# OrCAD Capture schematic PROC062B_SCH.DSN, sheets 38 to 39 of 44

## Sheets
38 38. TEST  HEADER: size C; title: TEST HEADER
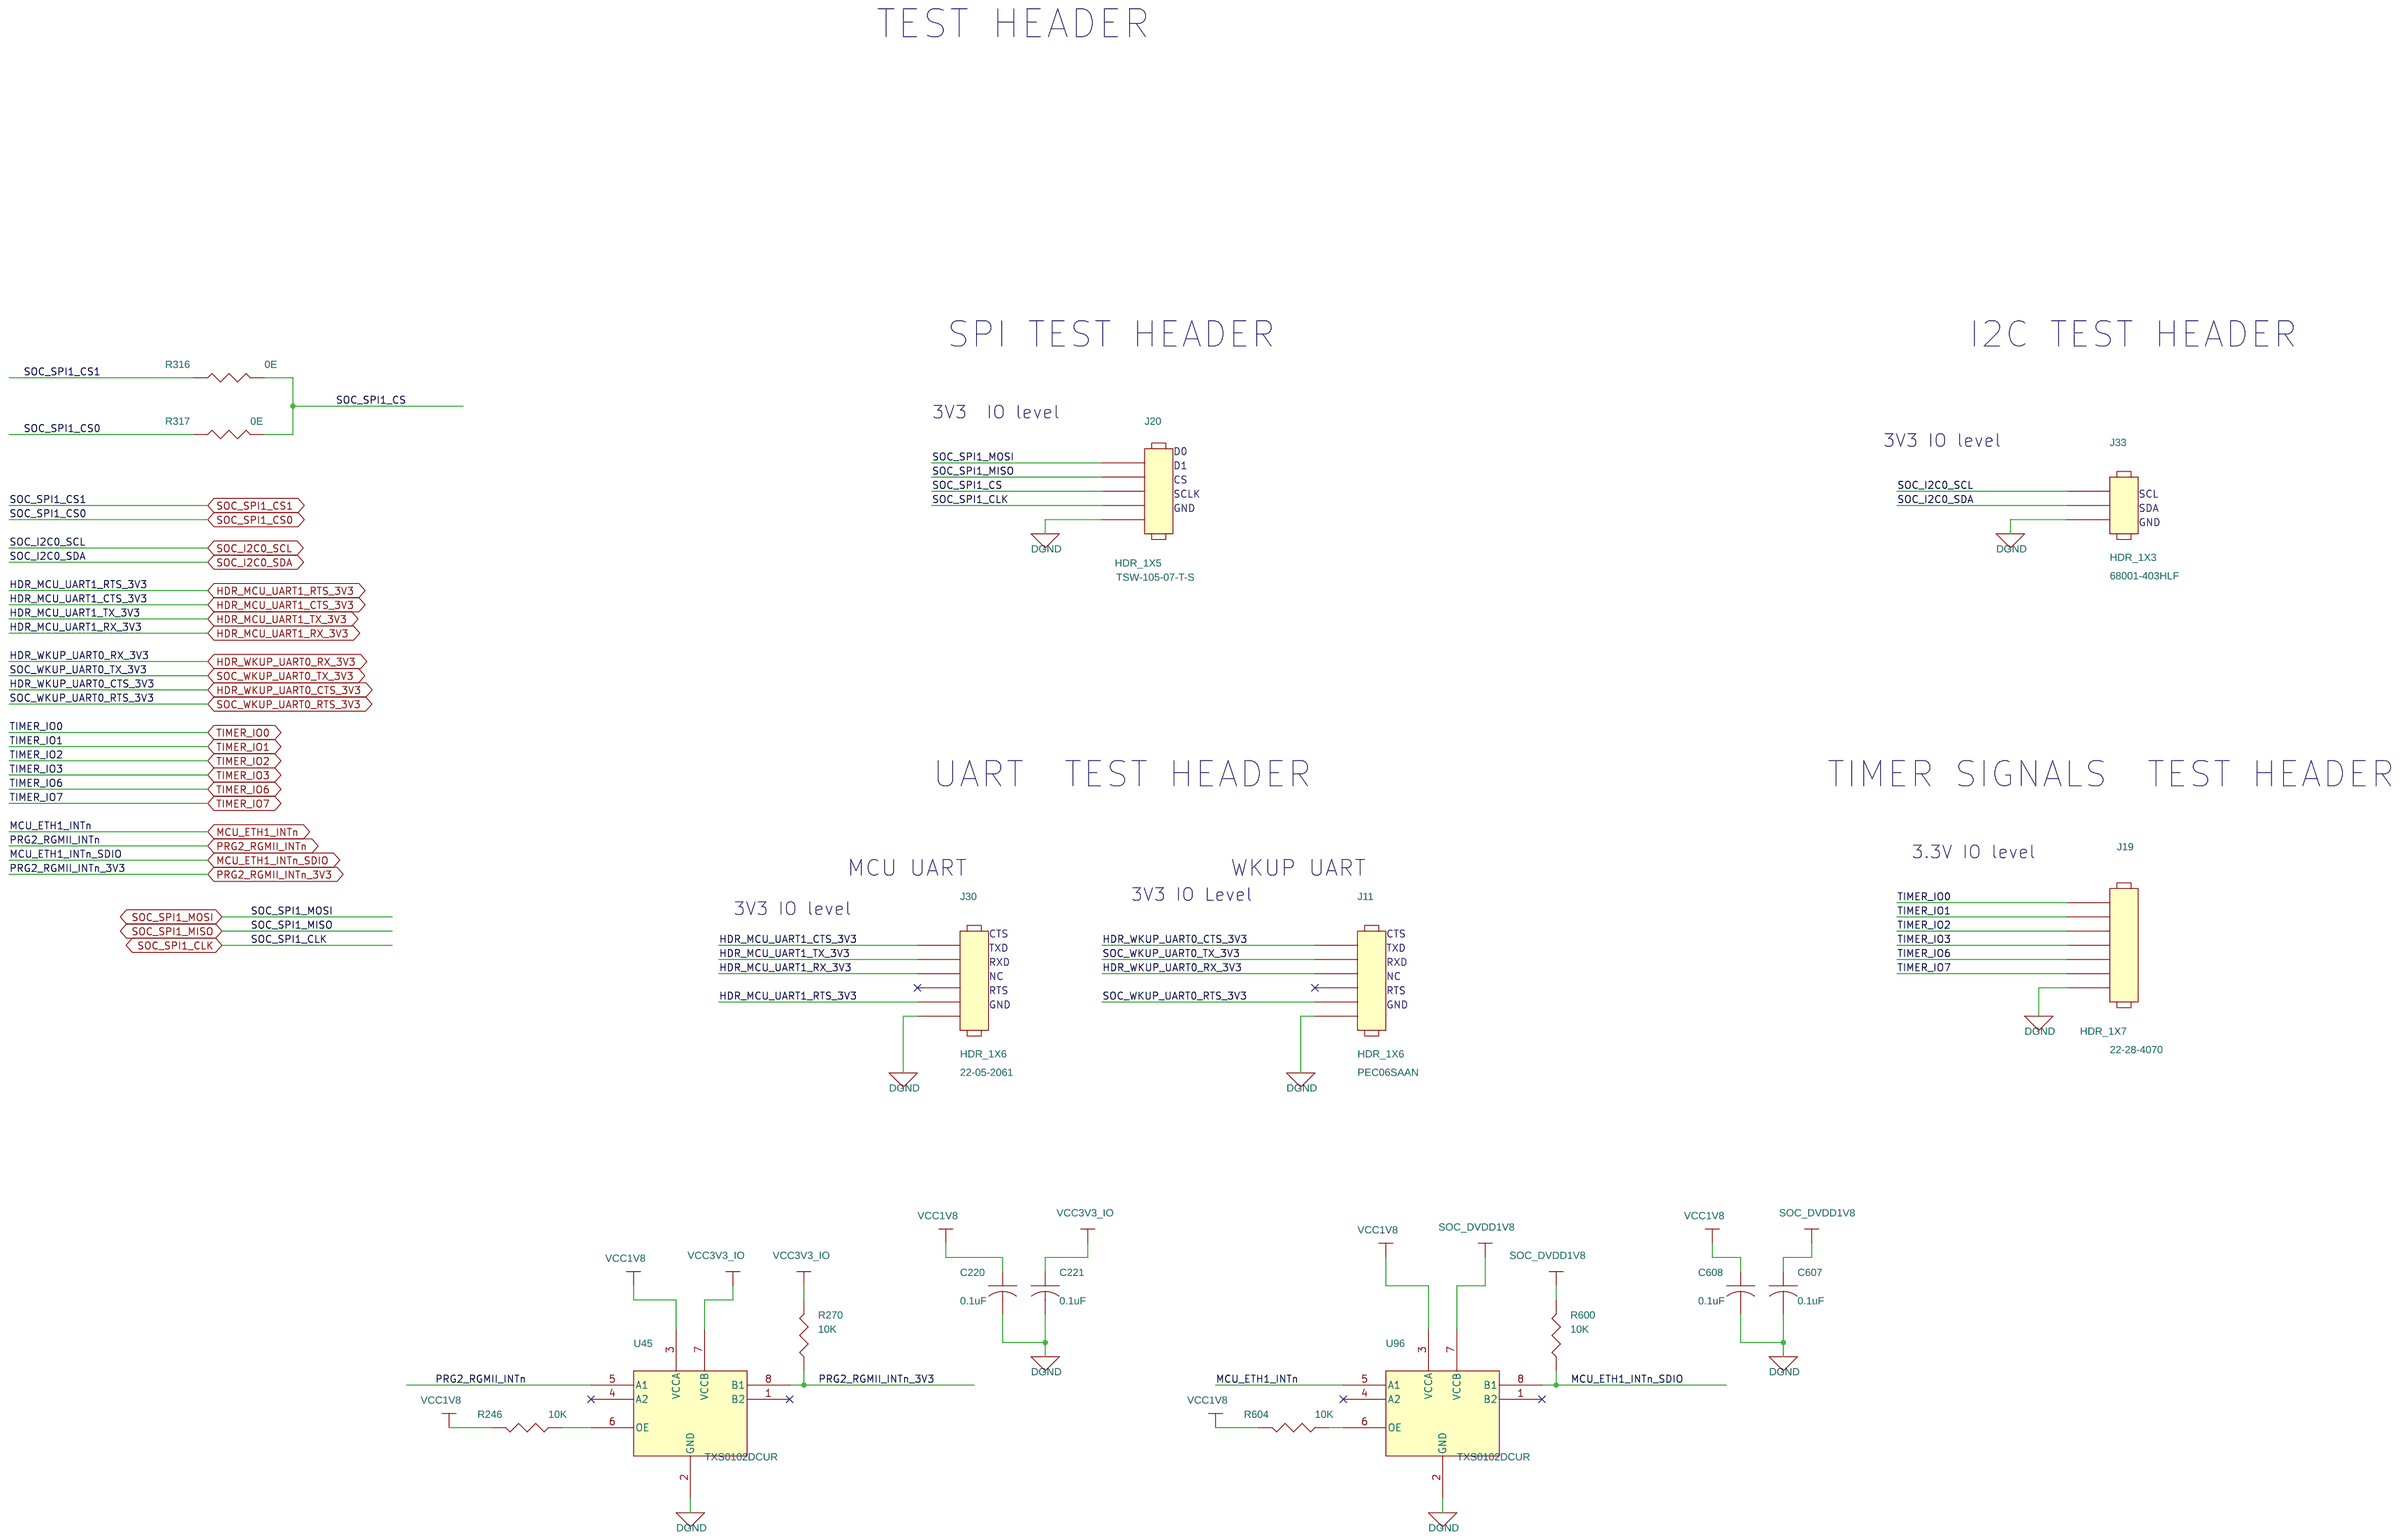
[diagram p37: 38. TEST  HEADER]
39 39. VOLTAGE SUPERVISOR: size C; title: VOLTAGE SUPERVISOR & WKUP LEDs
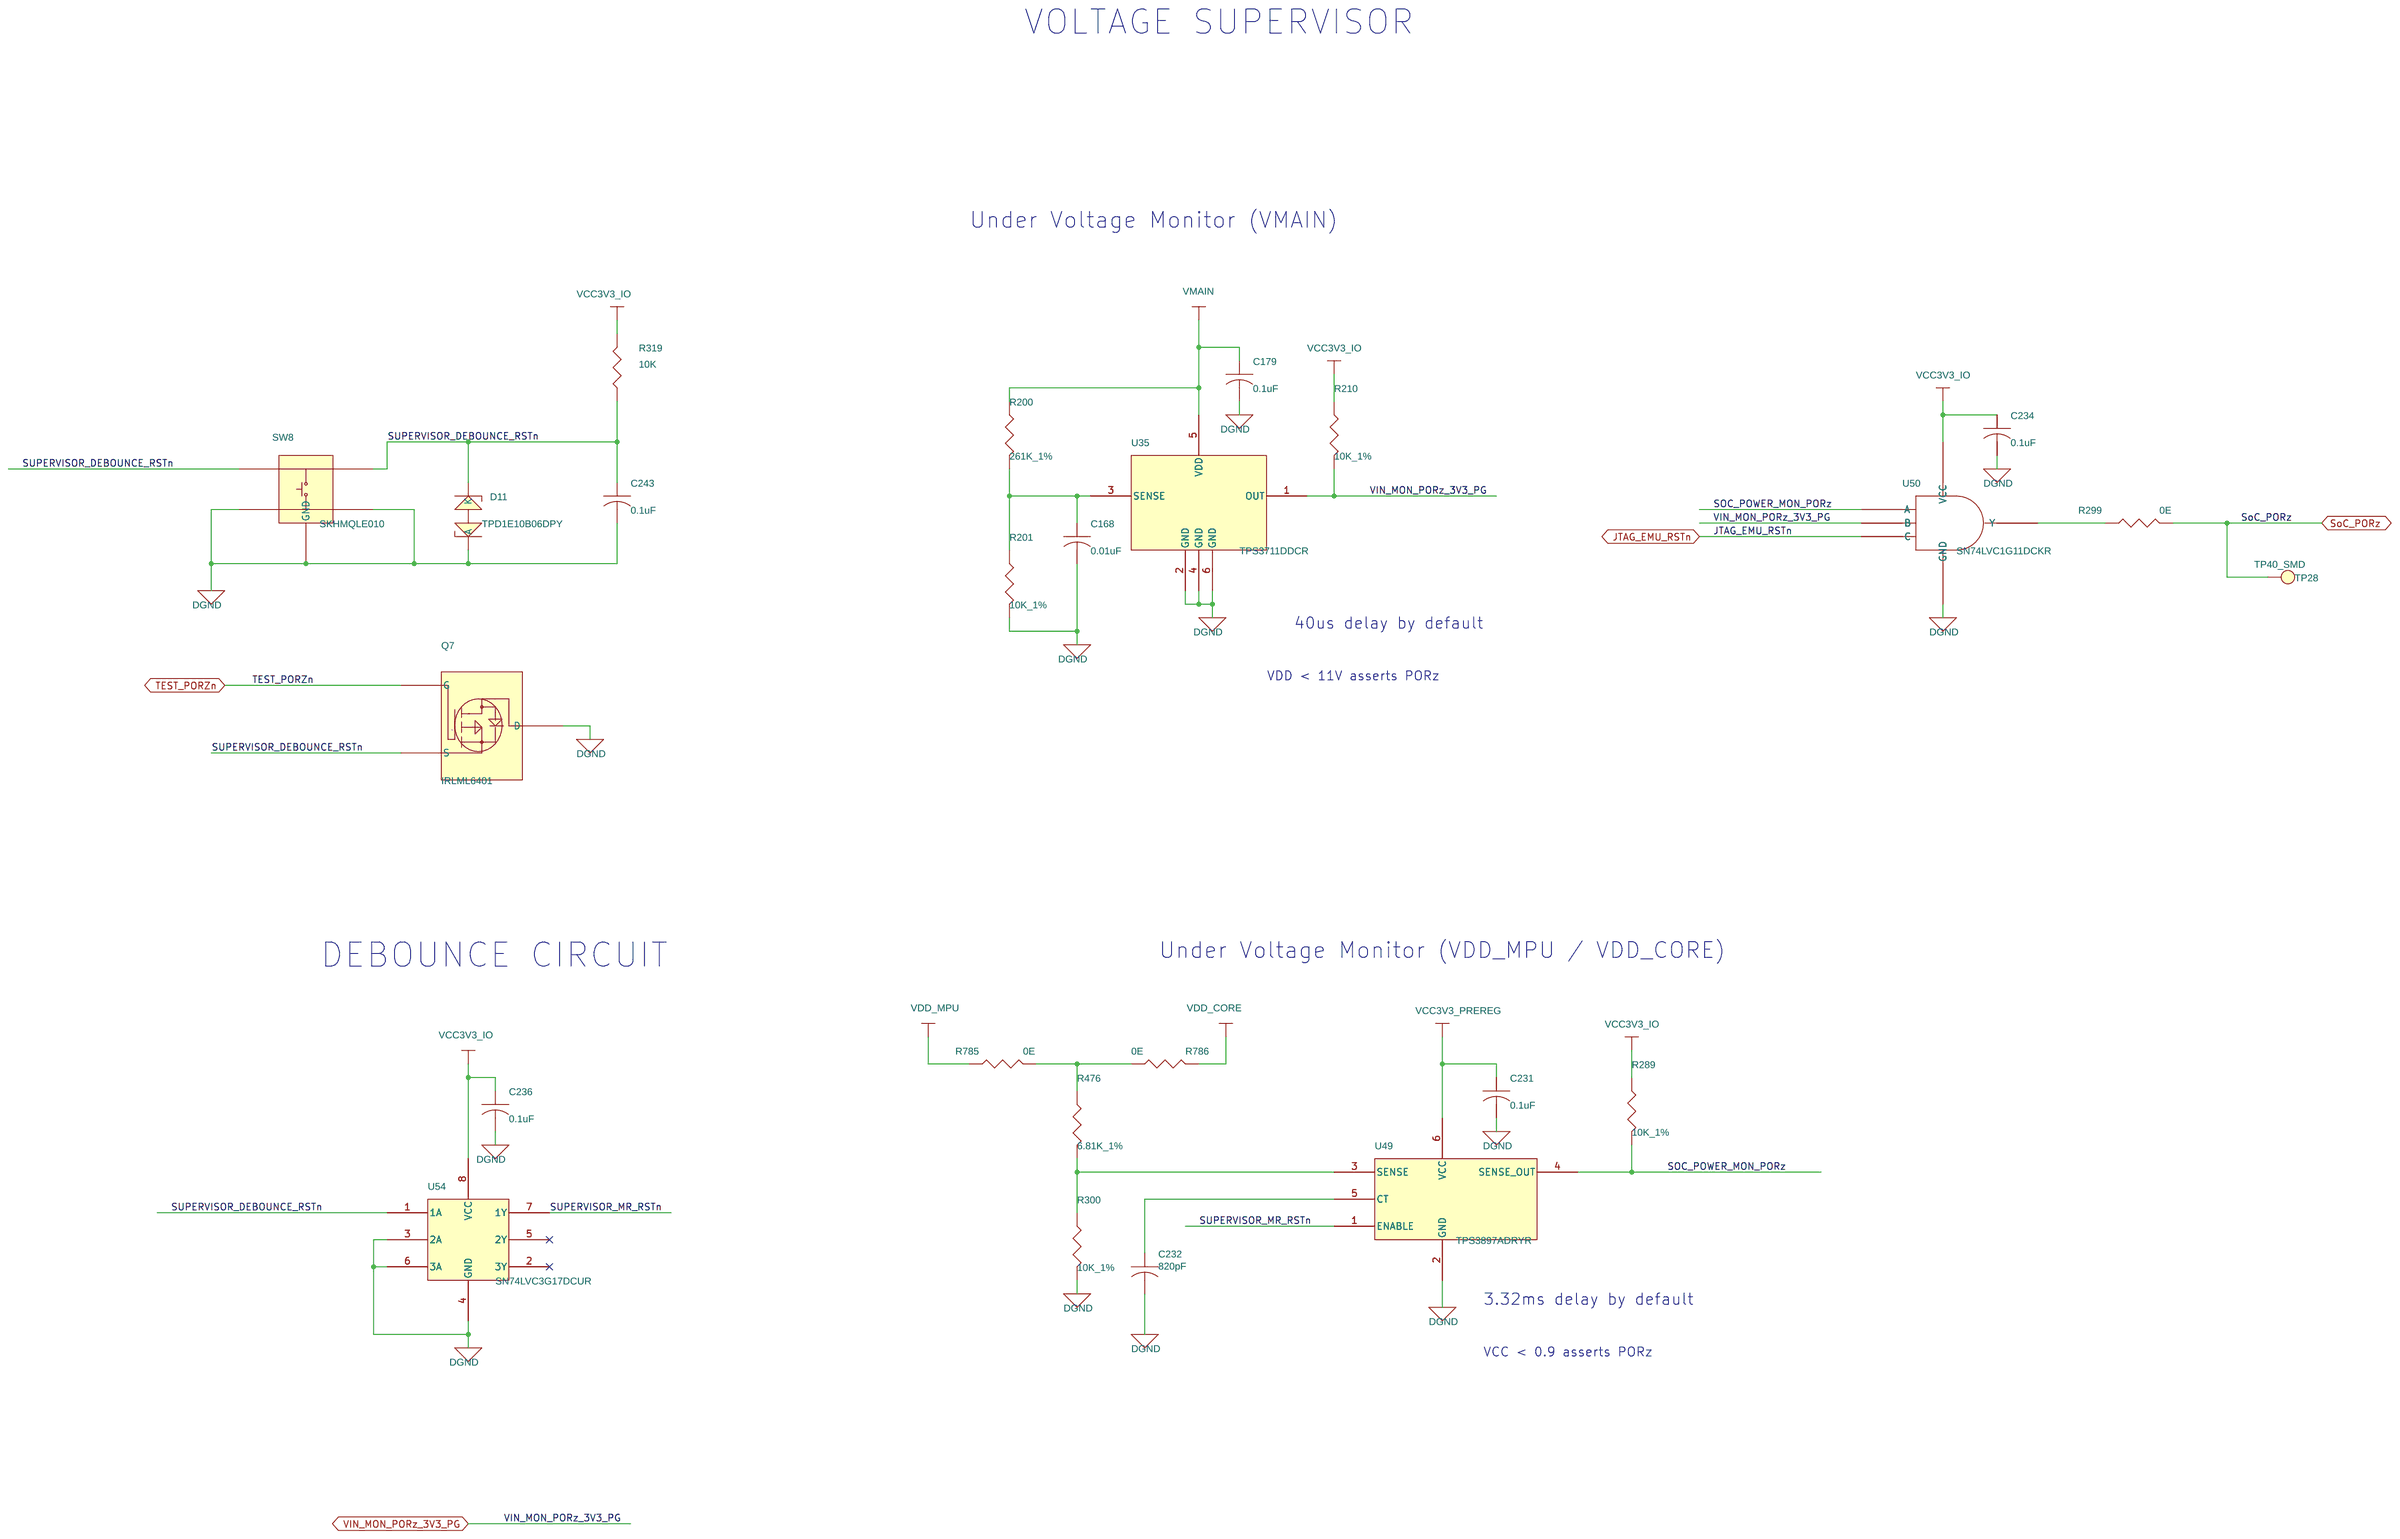
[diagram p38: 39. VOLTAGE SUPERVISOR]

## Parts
sheet 38. TEST  HEADER
C220  0.1uF  [CAP0201_0-5]
C221  0.1uF  [CAP0201_0-5]
C607  0.1uF  [CAP0201_0-5]
C608  0.1uF  [CAP0201_0-5]
J11  HDR_1X6  [HDR_6X1_100_S_T]
J19  HDR_1X7  [HDR_1X7_22284070_S_T_8-4]
J20  HDR_1X5  [HDR_5X1_100_S_T_8-4]
J30  HDR_1X6  [HDR_1X6_22052061_R_T_6-3]
J33  HDR_1X3  [HDR_3X1_100_S_T]
R246  10K  [RES0402_0-5]
R270  10K  [RES0402_0-5]
R316  0E  [RES0402_0-5]
R317  0E  [RES0402_0-5]
R600  10K  [RES0402_0-5]
R604  10K  [RES0402_0-5]
U45  TXS0102DCUR  [VSSOP8_19-68_85X95_0-9]
U96  TXS0102DCUR  [VSSOP8_19-68_85X95_0-9]
sheet 39. VOLTAGE SUPERVISOR
C168  0.01uF  [CAP0201_0-5]
C179  0.1uF  [CAP0603_1]
C231  0.1uF  [CAP0201_0-5]
C232  820pF  [CAP0402_0-75]
C234  0.1uF  [CAP0201_0-5]
C236  0.1uF  [CAP0201_0-5]
C243  0.1uF  [CAP0201_0-5]
D11  TPD1E10B06DPY  [DIO_DFN0402]
Q7  IRLML6401  [TO_SOT23-123]
R200  261K_1%  [RES0402_0-5]
R201  10K_1%  [RES0402_0-5]
R210  10K_1%  [RES0402_0-5]
R289  10K_1%  [RES0402_0-5]
R299  0E  [RES0402_0-5]
R300  10K_1%  [RES0402_0-5]
R319  10K  [RES0402_0-5]
R476  6.81K_1%  [RES0402_0-5]
R785  0E  [RES0402_0-5]
R786  0E  [RES0402_0-5]
SW8  SKHMQLE010  [SW4_SKHMQLE010_240X260_SMD_3-1]
TP28  TP40_SMD  [TP40_SMD]
U35  TPS3711DDCR  [SOT23-6_1-1]
U49  TPS3897ADRYR  [SON6_19-68_40X60_0-6]
U50  SN74LVC1G11DCKR  [SC70-6]
U54  SN74LVC3G17DCUR  [VSSOP8_19-68_85X95_0-9]

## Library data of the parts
C220 C221 C231 C234 C236 C243 C607 C608 = CAP: CAP CERAMIC 0.1uF 16V 10% X5R 0201; Chkd/date: MANIRAJA/120218; Crtd /date: MANIRAJA/120218; Custom_Duty: 15%; Customs_HS_Code: 85322990; Distributor_name: DIGIKEY; Distributor_part_number: 490-16742-1-ND; Height: 0.33MM; Mfr_name: MURATA; Mfr_part_number: GRM033R61C104KE84J; Mistral Part No: 120009030072-R; Package: 0201; Part_type: CAPACITORS\CERAMIC; Project: TI_MAXIE_CPB; RoHS: RoHS; Temperature: -55°C+85°C; Tolerance: 10%; Voltage: 16V; Wattage: NA; Weight: 0.33mg; Datasheet: Y:\MIS_DATABASE\DATASHEETS\CAPACITORS\GRM033R61C104KE84.PDF
J11 = HEADER_6X1: HDR 1X6 2.54 PITCH ST TH; Chkd/date: VASANTHA/220616; Crtd /date: VASANTHA/220616; Custom_Duty: 24%; Customs_HS_Code: 85369090; Distributor_name: DIGIKEY; Distributor_part_number: S1012E-06-ND; Height: 8.38MM; Mfr_name: SULLINS; Mfr_part_number: PEC06SAAN; Mistral Part No: 150016060022-R; Package: THRU HOLE; Part_type: CONNECTOR\HEADERS; Project: NTR_GPSDO BOX CARD; RoHS: RoHS; Temperature: -65°C+125°C; Tolerance: NA; Voltage: NA; Wattage: NA; Weight: NA; Datasheet: Y:\MIS_DATABASE\DATASHEETS\CONNECTORS\PECXXX_SERIES.PDF
J19 = HEADER_7X1: CON HDR 1X7 2.54MM PITCH ST TH; Chkd/date: MANIRAJA/230118; Crtd /date: ALVY/230118; Custom_Duty: 24%; Customs_HS_Code: 85369090; Distributor_name: DIGIKEY; Distributor_part_number: WM50014-07-ND; Height: 8.38MM; Mfr_name: MOLEX; Mfr_part_number: 22-28-4070; Mistral Part No: 150018010021-R; Package: THRU-HOLE; Part_type: CONNECTOR\HEADERS; Project: TI_MAXIE_CPB; RoHS: RoHS; Temperature: NA; Tolerance: NA; Voltage: NA; Wattage: NA; Weight: 431mg; Datasheet: Y:\MIS_DATABASE\DATASHEETS\CONNECTORS\22-28-SER.PDF
J20 = HEADER_5X1: CON HDR 1X5 2.54MM PITCH ST TH; Chkd/date: MANIRAJA/010917; Crtd /date: MANIRAJA/010917; Custom_Duty: 24%; Customs_HS_Code: 85369090; Distributor_name: DIGIKEY; Distributor_part_number: SAM1035-05-ND; Height: 8.38MM; Mfr_name: SAMTEC; Mfr_part_number: TSW-105-07-T-S; Mistral Part No: 150017090001-R; Package: THRU-HOLE; Part_type: CONNECTOR\HEADERS; Project: TI_MAXIE_CPB; RoHS: RoHS; Temperature: -55°C+105°C; Tolerance: NA; Voltage: NA; Wattage: NA; Weight: NA; Datasheet: Y:\MIS_DATABASE\DATASHEETS\CONNECTORS\TSW-MK.PDF
J30 = HEADER_6X1: CON HDR 1X6 2.54MM PITCH RT TH; Chkd/date: MANIRAJA/240118; Crtd /date: MANIRAJA/240118; Custom_Duty: 24%; Customs_HS_Code: 85369090; Distributor_name: DIGIKEY; Distributor_part_number: WM4104-ND; Height: 6.30MM; Mfr_name: MOLEX; Mfr_part_number: 22-05-2061; Mistral Part No: 150018010023-R; Package: THRU-HOLE; Part_type: CONNECTOR\HEADERS; Project: TI_MAXIE_CPB; RoHS: RoHS; Temperature: NA; Tolerance: NA; Voltage: NA; Wattage: NA; Weight: 484mg; Datasheet: Y:\MIS_DATABASE\DATASHEETS\CONNECTORS\A-4094-SER.PDF
J33 = HEADER_3X1: HDR 1X3 2.54MM PITCH ST TH; Chkd/date: VASANTHA/290616; Crtd /date: VASANTHA/290616; Custom_Duty: 15%; Customs_HS_Code: 85322990; Distributor_name: DIGIKEY; Distributor_part_number: 609-3471-ND; Height: 8.58MM; Mfr_name: FCI; Mfr_part_number: 68001-403HLF; Mistral Part No: 150016060025-R; Package: THRU-HOLE; Part_type: CONNECTOR\HEADERS; Project: IKEYP; RoHS: RoHS; Temperature: -40°C+105°C; Tolerance: NA; Voltage: NA; Wattage: NA; Weight: NA; Datasheet: Y:\MIS_DATABASE\DATASHEETS\CONNECTORS\68000.PDF
R246 R270 R319 R600 R604 = RESISTOR: RES 10K 1/16W 5% 0402; Chkd/date: VASANTHA/061216; Crtd /date: MAZHAR/230805; Custom_Duty: 15%; Customs_HS_Code: 85332119; Distributor_name: DIGIKEY; Distributor_part_number: 311-10KJRCT-ND; Footprint Path: Y:\MIS_DATABASE\Library\ALTIUM_TOOL\PCB_FOOTPRINTS\Altium_Footprint_Lib.PcbLib; Height: 0.40MM; Library Path: Y:\MIS_DATABASE\Library\ALTIUM_TOOL\SCHEMATICS_PARTS\MS_DISCRETE_Library.schlib; Mfr_name: YAGEO AMERICA; Mfr_part_number: RC0402JR-0710KL; Mistral Part No: 110009030208-R; Package: 0402; Part_type: RESISTORS\FIXED; Project: HSE; RoHS: Pb-Free; Temperature: -55°C+155°C; Tolerance: 5%; Voltage: NA; Wattage: 1/16W; Weight: 0.65mg; Datasheet: Y:\MIS_DATABASE\DATASHEETS\RESISTORS\YAGEO-RC0402.PDF
R299 R316 R317 R785 R786 = RESISTOR: RES 0E 1/16W 0402; Chkd/date: VASANTHA/201216; Crtd /date: MUDDU/190810; Custom_Duty: 15%; Customs_HS_Code: 85332119; Distributor_name: DIGIKEY; Distributor_part_number: 541-0.0JCT-ND; Footprint Path: Y:\MIS_DATABASE\Library\ALTIUM_TOOL\PCB_FOOTPRINTS\Altium_Footprint_Lib.PcbLib; Height: 0.40MM; Library Path: Y:\MIS_DATABASE\Library\ALTIUM_TOOL\SCHEMATICS_PARTS\MS_DISCRETE_Library.schlib; Mfr_name: VISHAY; Mfr_part_number: CRCW04020000Z0ED; Mistral Part No: 110010080019-P; Package: 0402; Part_type: RESISTORS\FIXED; Project: PB_BUGBASE; RoHS: Pb-Free; Temperature: -55°C+155°C; Tolerance: NA; Voltage: NA; Wattage: 1/16W; Weight: 0.65g/1000pcs; Datasheet: Y:\MIS_DATABASE\DATASHEETS\RESISTORS\CRCW0603.PDF
U45 U96 = TXS0102DCUR_VSSOP8: IC 2BIT BI-DIR VOLTAGE-LEVEL TRANSLATOR US8(VSSOP8); Chkd/date: MANIRAJA/130617; Crtd /date: SHREESHAIL/190108; Custom_Duty: 15%; Customs_HS_Code: 85423100; Distributor_name: DIGIKEY; Distributor_part_number: 296-21931-1-ND; Footprint Path: Y:\MIS_DATABASE\Library\ALTIUM_TOOL\PCB_FOOTPRINTS\Altium_Footprint_Lib.PcbLib; Height: 0.90MM; Library Path: Y:\MIS_DATABASE\Library\ALTIUM_TOOL\SCHEMATICS_PARTS\MS_MISCINTERFACE_Library.schlib; Mfr_name: TEXAS INSTRUMENTS; Mistral Part No: 141009030376-R; Package: US8; Part_type: ICS\INTERFACE\LEVEL TRANSLATOR; Project: SD_WATERLOO; RoHS: RoHS; Temperature: -40°C+85°C; Tolerance: NA; Voltage: NA; Wattage: NA; Weight: 9.6mg; Datasheet: Y:\MIS_DATABASE\DATASHEETS\ICS\INTERFACE\TXS0102.PDF
C168 = CAP: CAP CERAMIC 0.01uF 25V 10% X5R 0201; Chkd/date: MANIRAJA/230118; Crtd /date: MANIRAJA/230118; Custom_Duty: 15%; Customs_HS_Code: 85322990; Distributor_name: DIGIKEY; Distributor_part_number: GRM033R61E103KA12J-ND; Height: 0.33MM; Mfr_name: MURATA; Mfr_part_number: GRM033R61E103KA12J; Mistral Part No: 120018010007-R; Package: 0201; Part_type: CAPACITORS\CERAMIC; Project: TI_MAXIE_CPB; RoHS: RoHS; Temperature: -55°C+85°C; Tolerance: 10%; Voltage: 25V; Wattage: NA; Weight: 0.33mg; Datasheet: Y:\MIS_DATABASE\DATASHEETS\CAPACITORS\GRM033R61E103KA12.PDF
C179 = CAP: CAP CERAMIC 0.1uF 50V 20% X7R 0603; Chkd/date: MANIRAJA/240118; Crtd /date: MANIRAJA/240118; Custom_Duty: 15%; Customs_HS_Code: 85322990; Distributor_name: DIGIKEY; Distributor_part_number: 399-7845-1-ND; Height: 0.95MM; Mfr_name: KEMET; Mfr_part_number: C0603C104M5RACTU; Mistral Part No: 120018010021-R; Package: 0603; Part_type: CAPACITORS\CERAMIC; Project: TI_MAXIE_CPB; RoHS: RoHS; Temperature: -55°C+125°C; Tolerance: 20%; Voltage: 50V; Wattage: NA; Weight: 2mg; Datasheet: Y:\MIS_DATABASE\DATASHEETS\CAPACITORS\KEMET-X7R-SER.PDF
C232 = CAP: CAP CERAMIC 820pF 50V 5% C0G(NP0) AUTO 0402; Chkd/date: MANIRAJA/070220; Crtd /date: ALVY/070220; Custom_Duty: 15%; Customs_HS_Code: 85322990; Distributor_name: DIGIKEY; Distributor_part_number: 445-12152-1-ND; Footprint Path: Y:\MIS_DATABASE\Library\ALTIUM_TOOL\PCB_FOOTPRINTS\Altium_Footprint_Lib.PcbLib; Height: 0.55MM; Library Path: Y:\MIS_DATABASE\Library\ALTIUM_TOOL\SCHEMATICS_PARTS\MS_DISCRETE_Library.schlib; Mfr_name: TDK CORPORATION; Mfr_part_number: CGA2B2NP01H821J050BA; Mistral Part No: 120020020001-R; Package: 0402; Part_type: CAPACITORS\CERAMIC; Project: TI_MAXIE_CPB; RoHS: RoHS; Temperature: -55°C+150°C; Tolerance: 5%; Voltage: 50V; Wattage: NA; Weight: 0.65mg; Datasheet: Y:\MIS_DATABASE\DATASHEETS\CAPACITORS\CGA2B2NP01H821J050BA.PDF
D11 = DIODE_PESD: DIODE 1CH ESD PROTECTION SMD(0402); Chkd/date: USMAN/021214; Crtd /date: VASANTHA/181114; Custom_Duty: 15%; Customs_HS_Code: 85423100; Distributor_name: DIGIKEY; Distributor_part_number: 296-30406-1-ND; Height: 0.45MM; Mfr_name: TEXAS INSTRUMENTS; Mistral Part No: 130014110022-R; Package: SMD; Part_type: DIODE\MISC; Project: GALILEO_EVM; RoHS: RoHS; Temperature: -40°C+125°C; Tolerance: NA; Voltage: NA; Wattage: NA; Weight: NA; Datasheet: Y:\MIS_DATABASE\DATASHEETS\ICS\INTERFACE\TPD1E10B06.PDF
Q7 = MOSFET_IRLML6401TR: TRANSISTOR MOSFET P-CHANNEL SOT23-3; Chkd/date: SHREESHAIL/020206; Crtd /date: MAZHAR/040505; Custom_Duty: 15%; Customs_HS_Code: 85412900; Distributor_name: DIGIKEY; Distributor_part_number: IRLML6401PBFCT-ND; Height: 1.11MM; Mfr_name: IRF; Mfr_part_number: IRLML6401TRPBF; Mistral Part No: 130009031213-P; Package: SOT23-3; Part_type: TRANSISTOR\MOSFET; Project: G4_SVGA; Remarks: Part# replaced from “IRLML6401TR” to “IRLML6401TRPBF” making as a Pb-free part. (BAVISH/220311).; RoHS: Pb-Free; Temperature: -55°C+150°C; Tolerance: NA; Voltage: NA; Wattage: NA; Weight: NA; Datasheet: Y:\MIS_DATABASE\DATASHEETS\DISCRETES\TRANSISTORS_FETS\IRLML6401.PDF
R200 = RESISTOR: RES 261K 1/16W 1% 0402; Chkd/date: MANIRAJA/101017; Crtd /date: JEBRAN/250815; Custom_Duty: 15%; Customs_HS_Code: 85332119; Distributor_name: DIGIKEY; Distributor_part_number: 311-261KLRCT-ND; Height: 0.40MM; Mfr_name: YAGEO AMERICA; Mfr_part_number: RC0402FR-07261KL; Mistral Part No: 110015080042-R; Package: 0402; Part_type: RESISTORS\FIXED; Project: OCTBTS3600; RoHS: RoHS; Temperature: -55°C+155°C; Tolerance: 1%; Voltage: NA; Wattage: 1/16W; Weight: 0.65mg; Datasheet: Y:\MIS_DATABASE\DATASHEETS\RESISTORS\YAGEO.PDF
R201 R210 R289 R300 = RESISTOR: RES 10K 1/16W 1% 0402; Chkd/date: VASANTHA/201216; Crtd /date: GEETHA/290506; Custom_Duty: 15%; Customs_HS_Code: 85332119; Distributor_name: DIGIKEY; Distributor_part_number: 311-10.0KLRTR-ND; Footprint Path: Y:\MIS_DATABASE\Library\ALTIUM_TOOL\PCB_FOOTPRINTS\Altium_Footprint_Lib.PcbLib; Height: 0.40MM; Library Path: Y:\MIS_DATABASE\Library\ALTIUM_TOOL\SCHEMATICS_PARTS\MS_DISCRETE_Library.schlib; Mfr_name: YAGEO AMERICA; Mfr_part_number: RC0402FR-0710KL; Mistral Part No: 110009030220-P; Package: 0402; Part_type: RESISTORS\FIXED; Project: VOCERA; RoHS: Pb-Free; Temperature: -55°C+155°C; Tolerance: 1%; Voltage: NA; Wattage: 1/16W; Weight: 0.65mg; Datasheet: Y:\MIS_DATABASE\DATASHEETS\RESISTORS\YAGEO-RC0402.PDF
R476 = RESISTOR: RES 6.81K 1/16W 1% 0402; Chkd/date: VASANTHA/181017; Crtd /date: VASANTHA/181017; Custom_Duty: 15%; Customs_HS_Code: 85332119; Distributor_name: DIGIKEY; Distributor_part_number: 311-6.81KLRCT-ND; Height: 0.40MM; Mfr_name: YAGEO AMERICA; Mfr_part_number: RC0402FR-076K81L; Mistral Part No: 110017100003-R; Package: 0402; Part_type: RESISTORS\FIXED; Project: TI_MAXIE_CPB; RoHS: RoHS; Temperature: -55°C+155°C; Tolerance: 1%; Voltage: NA; Wattage: 1/16W; Weight: NA; Datasheet: Y:\MIS_DATABASE\DATASHEETS\RESISTORS\YAGEO-RC0402.PDF
SW8 = SW4_SKHUPLE010: SWITCH TACTILE SPST ST SMD; Chkd/date: MANIRAJA/051017; Crtd /date: MANIRAJA/051017; Custom_Duty: 24%; Customs_HS_Code: 85369090; Distributor_name: MOUSER; Distributor_part_number: 688-SKHMQLE010; Height: 3.10MM; Mfr_name: ALPS; Mistral Part No: 130017100007-R; Package: SMD; Part_type: ELECTRO-MECHANICAL\SWITCH; Project: TI_MAXIE_CPB; RoHS: RoHS; Temperature: -30°C+85°C; Tolerance: NA; Voltage: NA; Wattage: NA; Weight: NA; Datasheet: Y:\MIS_DATABASE\DATASHEETS\MISC\SWITCHES\SKHMQLE010.PDF
TP28 = TESTPOINT: TESTPOINT CIR 40 SMD; Chkd/date: MAZHAR/190505; Crtd /date: MAZHAR/190505; Distributor_name: NA; Distributor_part_number: NA; Footprint Path: Y:\MIS_DATABASE\Library\ALTIUM_TOOL\PCB_FOOTPRINTS\Altium_Footprint_Lib.PcbLib; Height: NA; Library Path: Y:\MIS_DATABASE\Library\ALTIUM_TOOL\SCHEMATICS_PARTS\MS_DISCRETE_Library.schlib; MECHANICAL 3D STEP FILE: NA; Mfr_name: LOCAL; Mistral Part No: 130009030933; Package: SMD; Project: RAINIER-3; RoHS: NA; Temperature: NA; Tolerance: NA; Voltage: NA; Wattage: NA; Weight: NA; Datasheet: NA
U35 = TPS3711DDCR_SOT23-6: IC 36V VOLTAGE DETECTOR SOT23-6; Chkd/date: MANIRAJA/091017; Crtd /date: MANIRAJA/091017; Custom_Duty: 15%; Customs_HS_Code: 85423100; Distributor_name: DIGIKEY; Distributor_part_number: 296-43278-1-ND; Height: 1.10MM; Mfr_name: TEXAS INSTRUMENTS; Mistral Part No: 142017100008-R; Package: SOT23-6; Part_type: ICS\POWER\MANAGEMENT; Project: TI_MAXIE_CPB; RoHS: RoHS; Temperature: -40°C+125°C; Tolerance: NA; Voltage: NA; Wattage: NA; Weight: 30mg; Datasheet: Y:\MIS_DATABASE\DATASHEETS\ICS\POWER\TPS3711D.PDF
U49 = TPS3897ADRYR_SON6: IC 1-CH ADJ VOLTAGE MONITOR SON6; Chkd/date: MANIRAJA/091017; Crtd /date: MANIRAJA/091017; Custom_Duty: 15%; Customs_HS_Code: 85423100; Distributor_name: DIGIKEY; Distributor_part_number: 296-29810-1-ND; Height: 0.60MM; Mfr_name: TEXAS INSTRUMENTS; Mistral Part No: 142017100007-R; Package: SON6; Part_type: ICS\POWER\MANAGEMENT; Project: TI_MAXIE_CPB; RoHS: RoHS; Temperature: -40°C+125°C; Tolerance: NA; Voltage: NA; Wattage: NA; Weight: NA; Datasheet: Y:\MIS_DATABASE\DATASHEETS\ICS\POWER\TPS389X.PDF
U50 = SN74LVC1G11DCKR_SC70-6: IC SINGLE 3-INPUT POSITIVE-AND GATE SC70-6; Chkd/date: SHREESHAIL/220506; Crtd /date: MAZHAR/150506; Custom_Duty: 15%; Customs_HS_Code: 85423100; Distributor_name: DIGIKEY; Distributor_part_number: 296-18066-1-ND; Height: 1.10MM; Mfr_name: TEXAS INSTRUMENTS; Mistral Part No: 141009030230-R; Part_type: ICS\DIGITAL\GATES; Project: VOCERA; RoHS: Sb/ Br FREE; Datasheet: Y:\MIS_DATABASE\DATASHEETS\ICS\DIGITAL\GATES\SN74LVC1G.PDF
U54 = SN74LVC3G17DCUR_VSSOP8: IC TRIPLE SCHMITT-TRIGGER BUFFER VSSOP8; Chkd/date: MANIRAJA/280917; Crtd /date: MANIRAJA/280917; Custom_Duty: 15%; Customs_HS_Code: 85423100; Distributor_name: DIGIKEY; Distributor_part_number: 296-18818-1-ND; Height: 0.90MM; Mfr_name: TEXAS INSTRUMENTS; Mistral Part No: 141017090019-R; Package: VSSOP8; Part_type: ICS\DIGITAL\COMBINATIONAL; Project: TI_MAXIE_CPB; RoHS: RoHS; Temperature: -40°C+125°C; Tolerance: NA; Voltage: NA; Wattage: NA; Weight: 9.6mg; Datasheet: Y:\MIS_DATABASE\DATASHEETS\ICS\DIGITAL\COMBINATIONAL\SN74LVC3G17.PDF

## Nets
DGND: C168.2 C179.2 C220.2 C221.2 C231.2 C232.2 C234.2 C236.2 C243.2 C607.2 C608.2 D11.2(A) J11.1 J19.7 J20.5 J30.1 J33.1 Q7.3(D) R201.2 R300.2 SW8.3 SW8.4 SW8.5(GND) U35.2(GND) U35.4(GND) U35.6(GND) U45.2(GND) U49.2(GND) U50.2(GND) U54.3(2A) U54.4(GND) U54.6(3A) U96.2(GND) ; also on sheet 11 12 13 14 15 16 17 18 19 20 21 22 23 24 25 26 27 28 29 30 31 32 33 34 35 36 37 40 41 42 43 44
VCC1V8: C220.1 C608.1 R246.2 R604.2 U45.3(VCCA) U96.3(VCCA) ; also on sheet 11 18 19 20 21 22 23 26 29 31 33 35 36 37 41 44
VCC3V3_IO: C221.1 C234.1 C236.1 R210.1 R270.2 R289.1 R319.2 U45.7(VCCB) U50.5(VCC) U54.8(VCC) ; also on sheet 11 18 19 20 21 22 23 24 25 26 28 29 30 31 33 34 35 36 37 41 42 43 44
VCC3V3_PREREG: C231.1 U49.6(VCC) ; also on sheet 13 40 41 42
VDD_CORE: R786.1 ; also on sheet 12 13 26 41
VDD_MPU: R785.1 ; also on sheet 12 26 41
VIN_MON_PORz_3V3_PG: R210.2 U35.1(OUT) U50.3(B) ; also on sheet 41 42
HDR_MCU_UART1_CTS_3V3: J30.6 ; also on sheet 31
HDR_MCU_UART1_RTS_3V3: J30.2 ; also on sheet 31
HDR_MCU_UART1_RX_3V3: J30.4 ; also on sheet 31
HDR_MCU_UART1_TX_3V3: J30.5 ; also on sheet 31
HDR_WKUP_UART0_CTS_3V3: J11.6 ; also on sheet 31
HDR_WKUP_UART0_RX_3V3: J11.4 ; also on sheet 31
JTAG_EMU_RSTn: U50.6(C) ; also on sheet 29
MCU_ETH1_INTn: U96.5(A1) ; also on sheet 23
MCU_ETH1_INTn_SDIO: R600.1 U96.8(B1) ; also on sheet 18
PRG2_RGMII_INTn: U45.5(A1) ; also on sheet 21 22
PRG2_RGMII_INTn_3V3: R270.1 U45.8(B1) ; also on sheet 34
SOC_DVDD1V8: C607.1 R600.2 U96.7(VCCB) ; also on sheet 13 14 18 26
SOC_I2C0_SCL: J33.3 ; also on sheet 11 33 34 37
SOC_I2C0_SDA: J33.2 ; also on sheet 11 33 34 37
SoC_PORz: R299.2 TP28.1(TP) ; also on sheet 34 35
SOC_POWER_MON_PORz: R289.2 U49.4(SENSE_OUT) U50.1(A)
SOC_SPI1_CLK: J20.4 ; also on sheet 34 35 44
SOC_SPI1_CS: J20.3 R316.1 R317.1
SOC_SPI1_CS0: R317.2 ; also on sheet 34 35
SOC_SPI1_CS1: R316.2 ; also on sheet 34 44
SOC_SPI1_MISO: J20.2 ; also on sheet 34 35 44
SOC_SPI1_MOSI: J20.1 ; also on sheet 34 35 44
SOC_WKUP_UART0_RTS_3V3: J11.2 ; also on sheet 31 34
SOC_WKUP_UART0_TX_3V3: J11.5 ; also on sheet 31 34
SUPERVISOR_DEBOUNCE_RSTn: C243.1 D11.1(K) Q7.2(S) R319.1 SW8.1 SW8.2 U54.1(1A)
SUPERVISOR_MR_RSTn: U49.1(ENABLE) U54.7(1Y)
TEST_PORZn: Q7.1(G) ; also on sheet 24
TIMER_IO0: J19.1 ; also on sheet 34
TIMER_IO1: J19.2 ; also on sheet 34
TIMER_IO2: J19.3 ; also on sheet 44
TIMER_IO3: J19.4 ; also on sheet 44
TIMER_IO6: J19.5 ; also on sheet 44
TIMER_IO7: J19.6 ; also on sheet 44
VMAIN: C179.1 R200.1 U35.5(VDD) ; also on sheet 40 42 43
N18289329: R300.1 R476.2 U49.3(SENSE)
N18289350: C232.1 U49.5(CT)
N18292398: C168.1 R200.2 R201.1 U35.3(SENSE)
N19158110: R299.1 U50.4(Y)
N20155231: R246.1 U45.6(OE)
N20155262: R604.1 U96.6(OE)
N23888383: R476.1 R785.2 R786.2

Not connected (* = marked no-connect by the designer): J11 3*; J30 3*; U45 1(B2)* 4(A2)*; U54 2(3Y)* 5(2Y)*; U96 1(B2)* 4(A2)*

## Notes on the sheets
sheet 38
- TEST HEADER
- SPI TEST HEADER
- I2C TEST HEADER
- 3V3  IO level
- D0
- 3V3 IO level
- D1
- CS
- SCLK
- SCL
- GND
- SDA
- GND
- UART  TEST HEADER
- TIMER SIGNALS  TEST HEADER
- 3.3V IO level
- MCU UART
- WKUP UART
- 3V3 IO Level
- 3V3 IO level
- CTS
- CTS
- TXD
- TXD
- RXD
- RXD
- NC
- NC
- GND
- RTS
- GND
- RTS
sheet 39
- VOLTAGE SUPERVISOR
- Under Voltage Monitor (VMAIN)
- 40us delay by default
- VDD < 11V asserts PORz
- DEBOUNCE CIRCUIT
- Under Voltage Monitor (VDD_MPU / VDD_CORE)
- 3.32ms delay by default
- VCC < 0.9 asserts PORz
